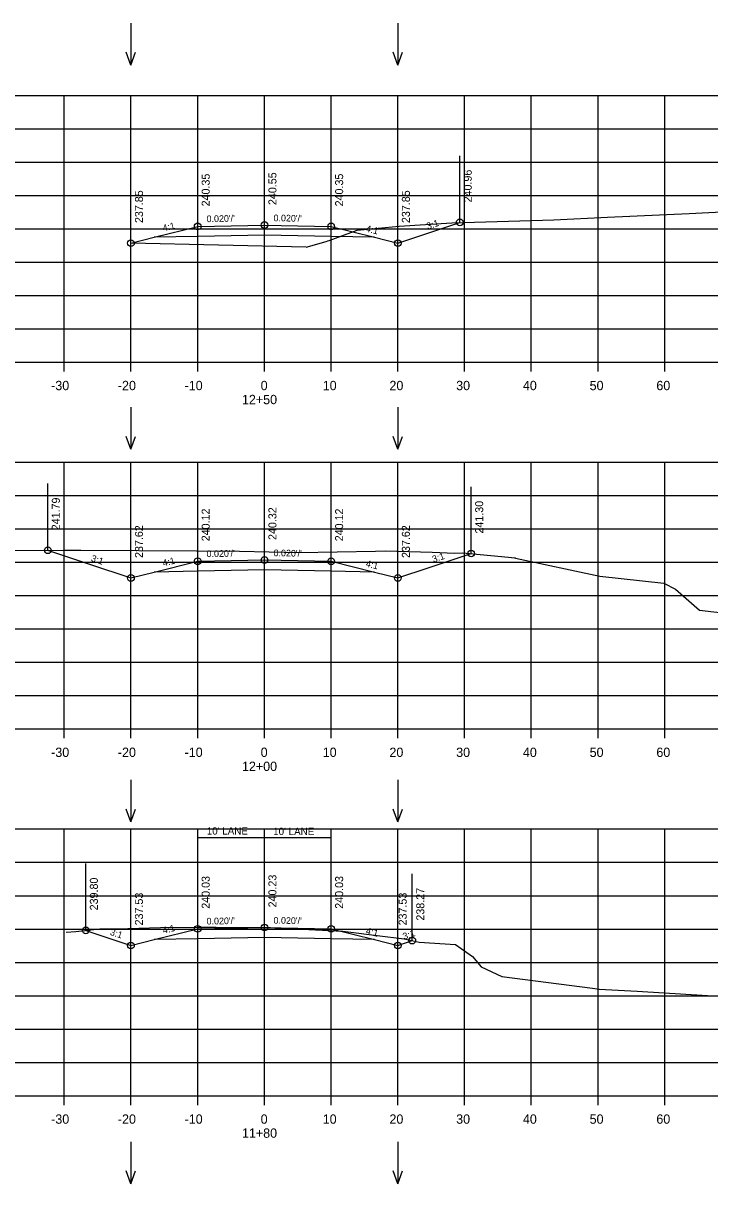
# Model space of a CAD drawing. Extents: x 1342547 to 1344156, y -1532351 to -1517216.
# Drawn here: x 1343042 to 1343144.9, y -1532348.1 to -1532174.1 of the extents above; entities that cross this region are included whole.
import ezdxf

# ---------------------------------------------------------------- set-up
doc = ezdxf.new("R2010")
doc.units = 0
for name, color, linetype in [('R_Alt Surface', 7, 'Continuous'), ('R_Axis', 7, 'Continuous'), ('R_Axis Annot', 7, 'Continuous'), ('R_Exist Surface', 7, 'Continuous'), ('R_Fin Surface', 7, 'Continuous'), ('R_Grid', 7, 'Continuous'), ('R_No Plot', 7, 'Continuous'), ('R_Water', 7, 'Continuous'), ('R_Xsect Elev', 7, 'Continuous'), ('R_Xsect Slope', 7, 'Continuous')]:
    doc.layers.add(name, color=color, linetype=linetype)

msp = doc.modelspace()

# ---------------------------------------------------------------- linework, layer by layer
at = {"layer": 'R_Alt Surface'}
for points in [[(1343094.71, -1532206.21), (1343088.19, -1532206.08), (1343078.19, -1532205.88), (1343068.19, -1532206.08), (1343061.67, -1532206.21)], [(1343094.71, -1532256.43), (1343088.19, -1532256.3), (1343078.19, -1532256.1), (1343068.19, -1532256.3), (1343061.67, -1532256.43)], [(1343094.71, -1532311.53), (1343088.19, -1532311.4), (1343078.19, -1532311.2), (1343068.19, -1532311.4), (1343061.67, -1532311.53)]]:
    msp.add_lwpolyline(points, dxfattribs=at)
at = {"layer": 'R_Axis'}
for p, q in [((1342938.19, -1532224.94), (1343218.19, -1532224.94)), ((1343048.19, -1532226.34), (1343048.19, -1532224.94)), ((1343058.19, -1532226.34), (1343058.19, -1532224.94)), ((1343068.19, -1532226.34), (1343068.19, -1532224.94)), ((1343078.19, -1532226.34), (1343078.19, -1532224.94)), ((1343088.19, -1532226.34), (1343088.19, -1532224.94)), ((1343098.19, -1532226.34), (1343098.19, -1532224.94)), ((1343108.19, -1532226.34), (1343108.19, -1532224.94)), ((1343118.19, -1532226.34), (1343118.19, -1532224.94)), ((1343128.19, -1532226.34), (1343128.19, -1532224.94)), ((1343138.19, -1532226.34), (1343138.19, -1532224.94)), ((1342938.19, -1532279.94), (1343218.19, -1532279.94)), ((1343048.19, -1532281.34), (1343048.19, -1532279.94)), ((1343058.19, -1532281.34), (1343058.19, -1532279.94)), ((1343068.19, -1532281.34), (1343068.19, -1532279.94)), ((1343078.19, -1532281.34), (1343078.19, -1532279.94)), ((1343088.19, -1532281.34), (1343088.19, -1532279.94)), ((1343098.19, -1532281.34), (1343098.19, -1532279.94)), ((1343108.19, -1532281.34), (1343108.19, -1532279.94)), ((1343118.19, -1532281.34), (1343118.19, -1532279.94)), ((1343128.19, -1532281.34), (1343128.19, -1532279.94)), ((1343138.19, -1532281.34), (1343138.19, -1532279.94)), ((1342938.19, -1532334.94), (1343218.19, -1532334.94)), ((1343048.19, -1532336.34), (1343048.19, -1532334.94)), ((1343058.19, -1532336.34), (1343058.19, -1532334.94)), ((1343068.19, -1532336.34), (1343068.19, -1532334.94)), ((1343078.19, -1532336.34), (1343078.19, -1532334.94)), ((1343088.19, -1532336.34), (1343088.19, -1532334.94)), ((1343098.19, -1532336.34), (1343098.19, -1532334.94)), ((1343108.19, -1532336.34), (1343108.19, -1532334.94)), ((1343118.19, -1532336.34), (1343118.19, -1532334.94)), ((1343128.19, -1532336.34), (1343128.19, -1532334.94)), ((1343138.19, -1532336.34), (1343138.19, -1532334.94))]:
    msp.add_line(p, q, dxfattribs=at)
at = {"layer": 'R_Exist Surface'}
for points in [[(1343084.47, -1532207.71), (1343087.46, -1532206.85), (1343087.7, -1532206.75), (1343087.89, -1532206.7), (1343092.09, -1532205.14), (1343098.4, -1532204.53), (1343106.29, -1532204.02), (1343121.56, -1532203.57), (1343129.6, -1532203.2), (1343141.85, -1532202.63), (1343148.73, -1532202.29), (1343152.29, -1532202.12), (1343156.65, -1532201.69), (1343173.98, -1532200.1), (1343174.37, -1532200.06), (1343178.41, -1532199.56), (1343179.63, -1532199.44), (1343182.39, -1532199.46), (1343198.76, -1532197.87), (1343203.63, -1532197.36), (1343217.11, -1532195.96), (1343218, -1532195.92), (1343218.19, -1532195.91)], [(1343084.47, -1532207.71), (1343058.19, -1532207.08)], [(1343025.93, -1532253.23), (1343048.11, -1532253.14), (1343050.14, -1532253.14), (1343050.29, -1532253.14), (1343050.69, -1532253.14), (1343067.99, -1532253.23), (1343074.46, -1532253.27), (1343083.37, -1532253.46), (1343094.82, -1532253.26), (1343096.27, -1532253.25), (1343103.33, -1532253.41), (1343106.71, -1532253.58), (1343107.89, -1532253.51), (1343114.75, -1532254.19), (1343115.65, -1532254.29), (1343115.78, -1532254.3), (1343115.83, -1532254.32), (1343128.48, -1532257.01), (1343138.03, -1532258.08), (1343139.78, -1532259), (1343143.37, -1532262.13), (1343165.73, -1532264.71)], [(1343048.47, -1532310.41), (1343049.93, -1532310.29), (1343053.53, -1532309.93), (1343055.48, -1532309.92), (1343056.09, -1532309.9), (1343062.6, -1532309.7), (1343068.18, -1532309.66), (1343070.94, -1532309.66), (1343077.73, -1532309.69), (1343079.1, -1532309.71), (1343079.77, -1532309.74), (1343089.95, -1532310.25), (1343095.91, -1532311), (1343098.36, -1532311.32), (1343099.14, -1532311.41), (1343101.37, -1532311.9), (1343106.85, -1532312.24), (1343109.36, -1532314.06), (1343110.67, -1532315.61), (1343113.76, -1532317.04), (1343127.35, -1532318.81), (1343128.35, -1532318.98), (1343134.04, -1532319.28), (1343181.91, -1532322.23)]]:
    msp.add_lwpolyline(points, dxfattribs=at)
at = {"layer": 'R_Fin Surface'}
for points in [[(1343058.19, -1532207.08), (1343061.67, -1532206.21), (1343068.19, -1532204.58), (1343078.19, -1532204.38), (1343088.19, -1532204.58), (1343094.71, -1532206.21), (1343098.19, -1532207.08), (1343107.46, -1532203.98)], [(1343045.73, -1532253.15), (1343045.82, -1532253.18), (1343051.98, -1532255.24), (1343058.19, -1532257.3), (1343061.67, -1532256.43), (1343068.19, -1532254.8), (1343078.19, -1532254.6), (1343088.19, -1532254.8), (1343094.71, -1532256.43), (1343098.19, -1532257.3), (1343102.86, -1532255.75), (1343109.18, -1532253.64)], [(1343051.43, -1532310.14), (1343051.43, -1532310.14), (1343058.19, -1532312.4), (1343061.66, -1532311.53), (1343061.67, -1532311.53), (1343068.19, -1532309.9), (1343068.19, -1532309.9), (1343068.19, -1532309.9), (1343078.19, -1532309.7), (1343088.18, -1532309.9), (1343088.19, -1532309.9), (1343094.71, -1532311.53), (1343094.71, -1532311.53), (1343094.71, -1532311.53), (1343098.19, -1532312.4), (1343100.35, -1532311.68)]]:
    msp.add_lwpolyline(points, dxfattribs=at)
at = {"layer": 'R_Grid'}
for p, q in [((1342938.19, -1532184.94), (1343218.19, -1532184.94)), ((1342938.19, -1532184.94), (1343218.19, -1532184.94)), ((1343048.19, -1532224.94), (1343048.19, -1532184.94)), ((1343048.19, -1532224.94), (1343048.19, -1532184.94)), ((1343058.19, -1532224.94), (1343058.19, -1532184.94)), ((1343058.19, -1532224.94), (1343058.19, -1532184.94)), ((1343068.19, -1532224.94), (1343068.19, -1532184.94)), ((1343068.19, -1532224.94), (1343068.19, -1532184.94)), ((1343078.19, -1532224.94), (1343078.19, -1532184.94)), ((1343078.19, -1532224.94), (1343078.19, -1532184.94)), ((1343088.19, -1532224.94), (1343088.19, -1532184.94)), ((1343088.19, -1532224.94), (1343088.19, -1532184.94)), ((1343098.19, -1532224.94), (1343098.19, -1532184.94)), ((1343098.19, -1532224.94), (1343098.19, -1532184.94)), ((1343108.19, -1532224.94), (1343108.19, -1532184.94)), ((1343108.19, -1532224.94), (1343108.19, -1532184.94)), ((1343118.19, -1532224.94), (1343118.19, -1532184.94)), ((1343118.19, -1532224.94), (1343118.19, -1532184.94)), ((1343128.19, -1532224.94), (1343128.19, -1532184.94)), ((1343128.19, -1532224.94), (1343128.19, -1532184.94)), ((1343138.19, -1532224.94), (1343138.19, -1532184.94)), ((1343138.19, -1532224.94), (1343138.19, -1532184.94)), ((1342938.19, -1532189.94), (1343218.19, -1532189.94)), ((1342938.19, -1532189.94), (1343218.19, -1532189.94)), ((1342938.19, -1532194.94), (1343218.19, -1532194.94)), ((1342938.19, -1532194.94), (1343218.19, -1532194.94)), ((1342938.19, -1532199.94), (1343218.19, -1532199.94)), ((1342938.19, -1532199.94), (1343218.19, -1532199.94)), ((1342938.19, -1532204.94), (1343218.19, -1532204.94)), ((1342938.19, -1532204.94), (1343218.19, -1532204.94)), ((1342938.19, -1532209.94), (1343218.19, -1532209.94)), ((1342938.19, -1532209.94), (1343218.19, -1532209.94)), ((1342938.19, -1532214.94), (1343218.19, -1532214.94)), ((1342938.19, -1532214.94), (1343218.19, -1532214.94)), ((1342938.19, -1532219.94), (1343218.19, -1532219.94)), ((1342938.19, -1532219.94), (1343218.19, -1532219.94)), ((1342938.19, -1532224.94), (1343218.19, -1532224.94)), ((1342938.19, -1532224.94), (1343218.19, -1532224.94)), ((1342938.19, -1532239.94), (1343218.19, -1532239.94)), ((1343048.19, -1532279.94), (1343048.19, -1532239.94)), ((1343058.19, -1532279.94), (1343058.19, -1532239.94)), ((1343068.19, -1532279.94), (1343068.19, -1532239.94)), ((1343078.19, -1532279.94), (1343078.19, -1532239.94)), ((1343088.19, -1532279.94), (1343088.19, -1532239.94)), ((1343098.19, -1532279.94), (1343098.19, -1532239.94)), ((1343108.19, -1532279.94), (1343108.19, -1532239.94)), ((1343118.19, -1532279.94), (1343118.19, -1532239.94)), ((1343128.19, -1532279.94), (1343128.19, -1532239.94)), ((1343138.19, -1532279.94), (1343138.19, -1532239.94)), ((1342938.19, -1532244.94), (1343218.19, -1532244.94)), ((1342938.19, -1532249.94), (1343218.19, -1532249.94)), ((1342938.19, -1532254.94), (1343218.19, -1532254.94)), ((1342938.19, -1532259.94), (1343218.19, -1532259.94)), ((1342938.19, -1532264.94), (1343218.19, -1532264.94)), ((1342938.19, -1532269.94), (1343218.19, -1532269.94)), ((1342938.19, -1532274.94), (1343218.19, -1532274.94)), ((1342938.19, -1532279.94), (1343218.19, -1532279.94)), ((1342938.19, -1532294.94), (1343218.19, -1532294.94)), ((1342938.19, -1532294.94), (1343218.19, -1532294.94)), ((1343048.19, -1532334.94), (1343048.19, -1532294.94)), ((1343048.19, -1532334.94), (1343048.19, -1532294.94)), ((1343058.19, -1532334.94), (1343058.19, -1532294.94)), ((1343058.19, -1532334.94), (1343058.19, -1532294.94)), ((1343068.19, -1532334.94), (1343068.19, -1532294.94)), ((1343068.19, -1532334.94), (1343068.19, -1532294.94)), ((1343078.19, -1532334.94), (1343078.19, -1532294.94)), ((1343078.19, -1532334.94), (1343078.19, -1532294.94)), ((1343088.19, -1532334.94), (1343088.19, -1532294.94)), ((1343088.19, -1532334.94), (1343088.19, -1532294.94)), ((1343098.19, -1532334.94), (1343098.19, -1532294.94)), ((1343098.19, -1532334.94), (1343098.19, -1532294.94)), ((1343108.19, -1532334.94), (1343108.19, -1532294.94)), ((1343108.19, -1532334.94), (1343108.19, -1532294.94)), ((1343118.19, -1532334.94), (1343118.19, -1532294.94)), ((1343118.19, -1532334.94), (1343118.19, -1532294.94)), ((1343128.19, -1532334.94), (1343128.19, -1532294.94)), ((1343128.19, -1532334.94), (1343128.19, -1532294.94)), ((1343138.19, -1532334.94), (1343138.19, -1532294.94)), ((1343138.19, -1532334.94), (1343138.19, -1532294.94)), ((1342938.19, -1532299.94), (1343218.19, -1532299.94)), ((1342938.19, -1532299.94), (1343218.19, -1532299.94)), ((1342938.19, -1532304.94), (1343218.19, -1532304.94)), ((1342938.19, -1532304.94), (1343218.19, -1532304.94)), ((1342938.19, -1532309.94), (1343218.19, -1532309.94)), ((1342938.19, -1532309.94), (1343218.19, -1532309.94)), ((1342938.19, -1532314.94), (1343218.19, -1532314.94)), ((1342938.19, -1532314.94), (1343218.19, -1532314.94)), ((1342938.19, -1532319.94), (1343218.19, -1532319.94)), ((1342938.19, -1532319.94), (1343218.19, -1532319.94)), ((1342938.19, -1532324.94), (1343218.19, -1532324.94)), ((1342938.19, -1532324.94), (1343218.19, -1532324.94)), ((1342938.19, -1532329.94), (1343218.19, -1532329.94)), ((1342938.19, -1532329.94), (1343218.19, -1532329.94)), ((1342938.19, -1532334.94), (1343218.19, -1532334.94)), ((1342938.19, -1532334.94), (1343218.19, -1532334.94))]:
    msp.add_line(p, q, dxfattribs=at)
at = {"layer": 'R_No Plot'}
for centre in [(1343107.46, -1532203.98), (1343068.19, -1532204.58), (1343078.19, -1532204.38), (1343088.19, -1532204.58), (1343058.19, -1532207.08), (1343098.19, -1532207.08), (1343045.73, -1532253.15), (1343068.19, -1532254.8), (1343078.19, -1532254.6), (1343088.19, -1532254.8), (1343109.18, -1532253.64), (1343058.19, -1532257.3), (1343098.19, -1532257.3), (1343051.43, -1532310.14), (1343068.19, -1532309.9), (1343078.19, -1532309.7), (1343088.19, -1532309.9), (1343100.35, -1532311.68), (1343058.19, -1532312.4), (1343098.19, -1532312.4)]:
    msp.add_circle(centre, 0.5, dxfattribs=at)
at = {"layer": 'R_Water'}
for p, q in [((1343058.19, -1532174.11), (1343058.19, -1532180.39)), ((1343098.19, -1532174.11), (1343098.19, -1532180.39)), ((1343058.19, -1532180.39), (1343057.49, -1532178.47)), ((1343058.19, -1532180.39), (1343058.89, -1532178.47)), ((1343098.19, -1532180.39), (1343097.49, -1532178.47)), ((1343098.19, -1532180.39), (1343098.89, -1532178.47)), ((1343058.19, -1532231.7), (1343058.19, -1532237.99)), ((1343098.19, -1532231.7), (1343098.19, -1532237.99)), ((1343058.19, -1532237.99), (1343057.49, -1532236.06)), ((1343058.19, -1532237.99), (1343058.89, -1532236.06)), ((1343098.19, -1532237.99), (1343097.49, -1532236.06)), ((1343098.19, -1532237.99), (1343098.89, -1532236.06)), ((1343058.19, -1532287.59), (1343058.19, -1532293.88)), ((1343098.19, -1532287.59), (1343098.19, -1532293.88)), ((1343058.19, -1532293.88), (1343057.49, -1532291.95)), ((1343058.19, -1532293.88), (1343058.89, -1532291.95)), ((1343098.19, -1532293.88), (1343097.49, -1532291.95)), ((1343098.19, -1532293.88), (1343098.89, -1532291.95)), ((1343058.19, -1532341.86), (1343058.19, -1532348.14)), ((1343098.19, -1532341.86), (1343098.19, -1532348.14)), ((1343058.19, -1532348.14), (1343057.49, -1532346.22)), ((1343058.19, -1532348.14), (1343058.89, -1532346.22)), ((1343098.19, -1532348.14), (1343097.49, -1532346.22)), ((1343098.19, -1532348.14), (1343098.89, -1532346.22))]:
    msp.add_line(p, q, dxfattribs=at)
at = {"layer": 'R_Xsect Elev'}
for p, q in [((1343068.19, -1532204.58), (1343068.19, -1532194.58)), ((1343078.19, -1532204.38), (1343078.19, -1532194.38)), ((1343088.19, -1532204.58), (1343088.19, -1532194.58)), ((1343107.46, -1532203.98), (1343107.46, -1532193.98)), ((1343058.19, -1532207.08), (1343058.19, -1532197.08)), ((1343098.19, -1532207.08), (1343098.19, -1532197.08)), ((1343045.73, -1532253.15), (1343045.73, -1532243.15)), ((1343109.18, -1532253.64), (1343109.18, -1532243.64)), ((1343068.19, -1532254.8), (1343068.19, -1532244.8)), ((1343078.19, -1532254.6), (1343078.19, -1532244.6)), ((1343088.19, -1532254.8), (1343088.19, -1532244.8)), ((1343058.19, -1532257.3), (1343058.19, -1532247.3)), ((1343098.19, -1532257.3), (1343098.19, -1532247.3)), ((1343068.19, -1532309.9), (1343068.19, -1532295.39)), ((1343078.19, -1532309.7), (1343078.19, -1532295.39)), ((1343088.19, -1532309.9), (1343088.19, -1532295.39)), ((1343088.19, -1532296.27), (1343068.19, -1532296.27)), ((1343051.43, -1532310.14), (1343051.43, -1532300.14)), ((1343058.19, -1532312.4), (1343058.19, -1532302.4)), ((1343098.19, -1532312.4), (1343098.19, -1532302.4)), ((1343100.35, -1532311.68), (1343100.35, -1532301.68))]:
    msp.add_line(p, q, dxfattribs=at)

# ---------------------------------------------------------------- texts
at = {"layer": 'R_Axis Annot'}
for s, p in [('-30', (1343046.23, -1532229.14)), ('-20', (1343056.23, -1532229.14)), ('-10', (1343066.23, -1532229.14)), ('0', (1343077.63, -1532229.14)), ('10', (1343086.93, -1532229.14)), ('20', (1343096.93, -1532229.14)), ('30', (1343106.93, -1532229.14)), ('40', (1343116.93, -1532229.14)), ('50', (1343126.93, -1532229.14)), ('60', (1343136.93, -1532229.14)), ('12+50', (1343074.83, -1532231.24)), ('-30', (1343046.23, -1532284.14)), ('-20', (1343056.23, -1532284.14)), ('-10', (1343066.23, -1532284.14)), ('0', (1343077.63, -1532284.14)), ('10', (1343086.93, -1532284.14)), ('20', (1343096.93, -1532284.14)), ('30', (1343106.93, -1532284.14)), ('40', (1343116.93, -1532284.14)), ('50', (1343126.93, -1532284.14)), ('60', (1343136.93, -1532284.14)), ('12+00', (1343074.83, -1532286.24)), ('-30', (1343046.23, -1532339.14)), ('-20', (1343056.23, -1532339.14)), ('-10', (1343066.23, -1532339.14)), ('0', (1343077.63, -1532339.14)), ('10', (1343086.93, -1532339.14)), ('20', (1343096.93, -1532339.14)), ('30', (1343106.93, -1532339.14)), ('40', (1343116.93, -1532339.14)), ('50', (1343126.93, -1532339.14)), ('60', (1343136.93, -1532339.14)), ('11+80', (1343074.83, -1532341.24))]:
    msp.add_text(s, height=1.4, dxfattribs=at).set_placement(p)
at = {"layer": 'R_Xsect Elev'}
for s, p in [('240.35', (1343069.99, -1532201.58)), ('240.55', (1343079.99, -1532201.38)), ('240.35', (1343089.99, -1532201.58)), ('240.96', (1343109.26, -1532200.98)), ('237.85', (1343059.99, -1532204.08)), ('237.85', (1343099.99, -1532204.08)), ('241.79', (1343047.53, -1532250.15)), ('240.12', (1343069.99, -1532251.8)), ('240.32', (1343079.99, -1532251.6)), ('240.12', (1343089.99, -1532251.8)), ('241.30', (1343110.98, -1532250.64)), ('237.62', (1343059.99, -1532254.3)), ('237.62', (1343099.99, -1532254.3)), ('239.80', (1343053.23, -1532307.14)), ('240.03', (1343069.99, -1532306.9)), ('240.23', (1343079.99, -1532306.7)), ('240.03', (1343089.99, -1532306.9)), ('237.53', (1343059.99, -1532309.4)), ('237.53', (1343099.51, -1532309.4)), ('238.27', (1343102.15, -1532308.68))]:
    msp.add_text(s, height=1.2, rotation=90, dxfattribs=at).set_placement(p)
for p in [(1343069.55, -1532295.78), (1343079.5, -1532295.85)]:
    msp.add_text("10' LANE", height=1.1, dxfattribs=at).set_placement(p)
at = {"layer": 'R_Xsect Slope'}
for s, rotation, p in [("0.020'/'", 1.1458, (1343069.53, -1532203.95)), ("0.020'/'", 358.8542, (1343079.55, -1532203.8)), ('3:1', 18.4332, (1343102.67, -1532205.06)), ('4:1', 14.0362, (1343063.07, -1532205.34)), ('4:1', 345.9638, (1343093.31, -1532205.34)), ('3:1', 341.5668, (1343052.12, -1532254.75)), ('4:1', 14.0362, (1343063.07, -1532255.57)), ("0.020'/'", 1.1458, (1343069.53, -1532254.18)), ("0.020'/'", 358.8542, (1343079.55, -1532254.03)), ('3:1', 18.4332, (1343103.53, -1532255)), ('4:1', 345.9638, (1343093.31, -1532255.57)), ("0.020'/'", 1.1458, (1343069.53, -1532309.27)), ("0.020'/'", 358.8542, (1343079.55, -1532309.12)), ('3:1', 341.5668, (1343054.97, -1532310.79)), ('4:1', 14.0362, (1343063.07, -1532310.66)), ('4:1', 345.9638, (1343093.31, -1532310.66)), ('3:1', 18.4332, (1343099.11, -1532311.56))]:
    msp.add_text(s, height=1, rotation=rotation, dxfattribs=at).set_placement(p)

doc.saveas('drawing.dxf')
